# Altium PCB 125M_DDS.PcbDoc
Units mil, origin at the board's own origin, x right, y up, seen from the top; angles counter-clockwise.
Board outline 3579 x 1797 mil, 2 copper layers (Top Layer, Bottom Layer); 23 components, 27 nets, 92 pads, 0 vias.
Unrouted connection lines stored in the file: 63.
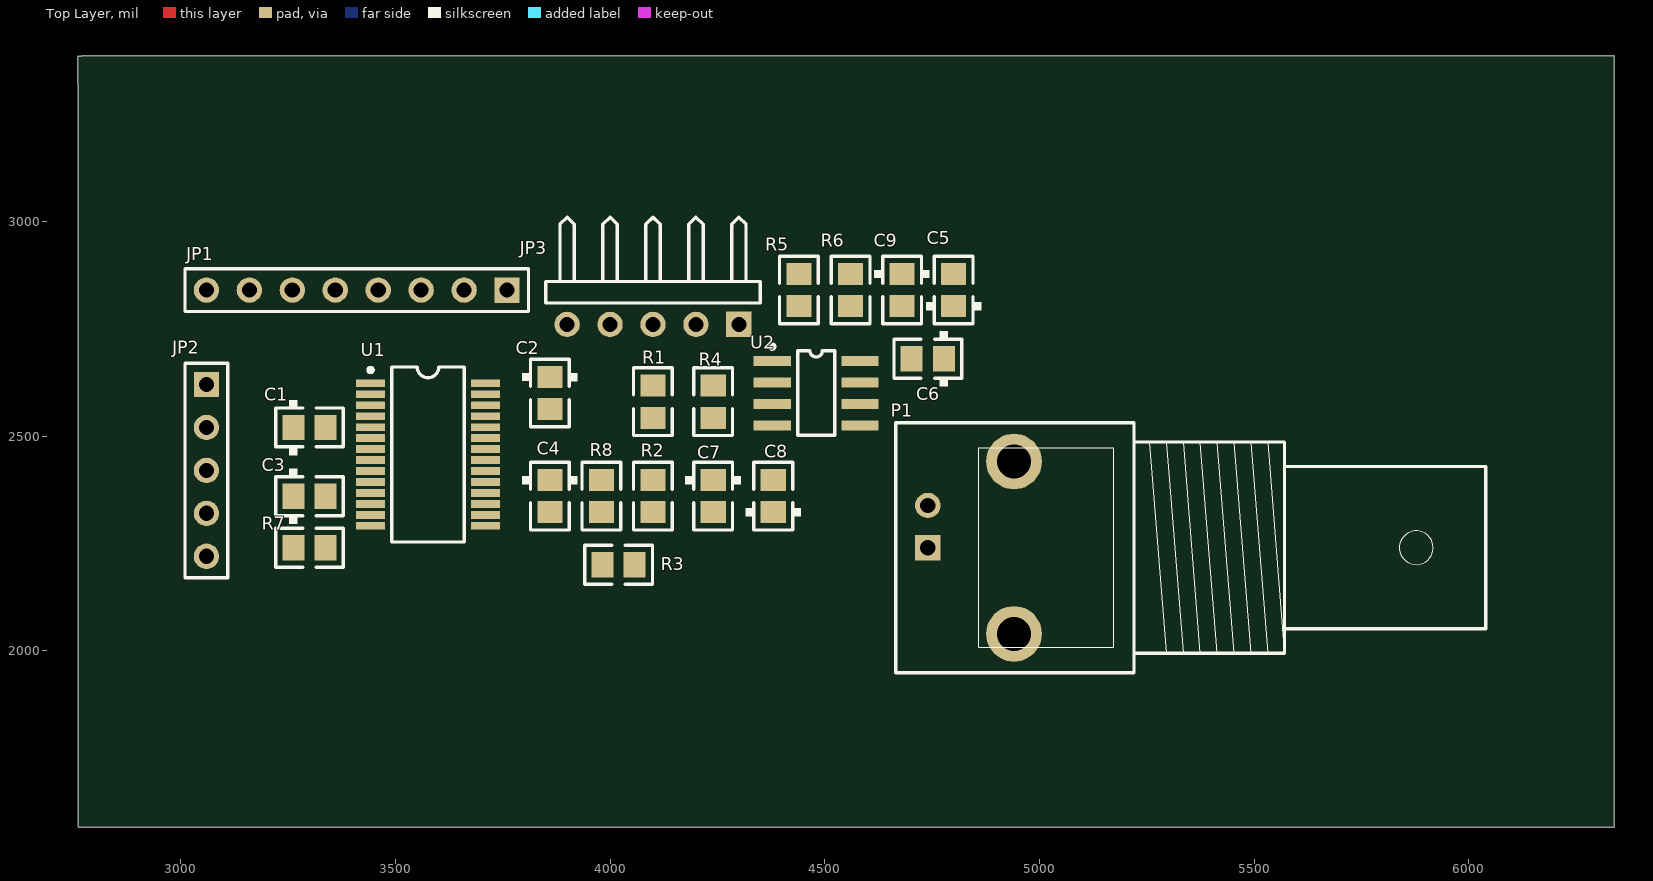
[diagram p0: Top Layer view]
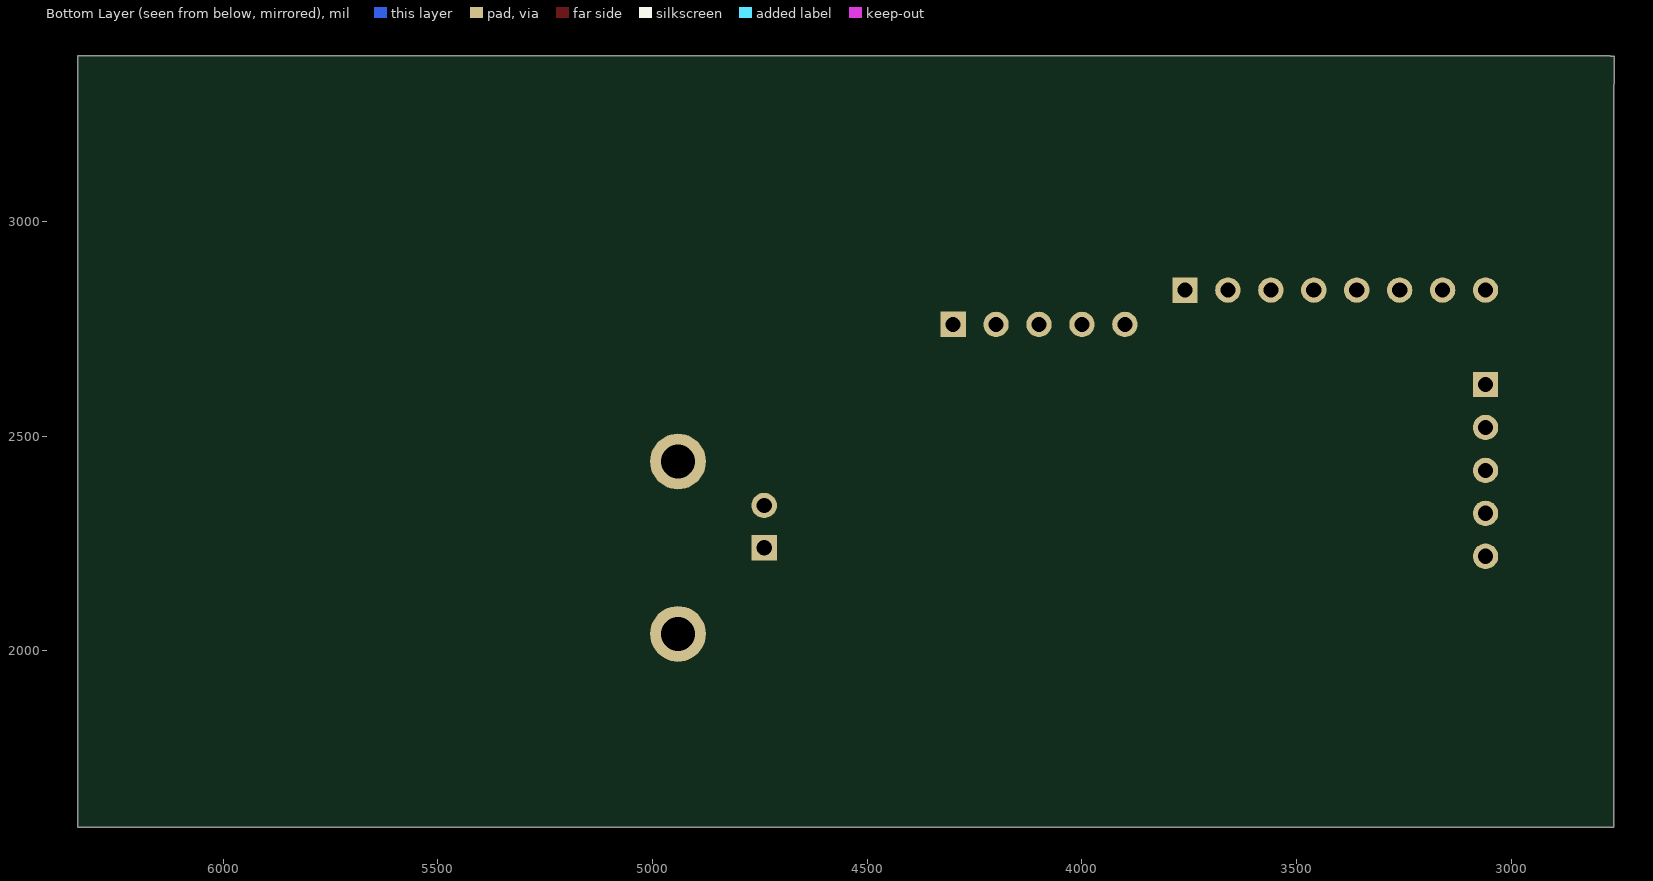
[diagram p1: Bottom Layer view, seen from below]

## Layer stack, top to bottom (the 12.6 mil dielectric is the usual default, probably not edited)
Top Layer: signal copper 1.4
Dielectric: dielectric 12.6, FR-4, Dk 4.8
Bottom Layer: signal copper 1.4

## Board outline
2761,3317 2761,1589 6339,1589 6339,3386 2770,3386 2770,3385 2760,3385 2760,3321

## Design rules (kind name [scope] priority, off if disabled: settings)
Clearance [All] p1: gap=5
ComponentClearance [All] p1: gap=10 collisioncheckmode=0
PolygonConnect [All] p1: connectstyle=Relief reliefconductorwidth=10 reliefentries=4 polygonreliefangle="90 Angle"
RoutingLayers [All] p1: top layer=Horizontal bottom layer=Vertical
RoutingVias [All] p1: holewidth=28 width=50 viastyle="Through Hole" minholewidth=28 minwidth=50 maxholewidth=28 maxwidth=50
SolderMaskExpansion [All] p1: expansion=4
TestPointUsage [All] p1: valid=0 allowmultiple=FALSE
Testpoint [All] p1: side=15 testpointundercomponent=TRUE minsize=40 maxsize=100 preferedsize=60 minholesize=0 maxholesize=40 preferedholesize=32 testpointgrid=1 style=1023 order=-539222988
Width [All] p1: maxlimit=10 minlimit=10 preferedwidth=10
16 further rules are at their usual default settings.

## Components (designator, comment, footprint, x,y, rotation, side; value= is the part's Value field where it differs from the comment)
C1 "100pF" CC2012-0805 3300,2520 r0 top
C2 "100pF" CC2012-0805 3860,2600 r270 top
C3 "100pF" CC2012-0805 3300,2360 r0 top
C4 "100pF" CC2012-0805 3860,2360 r270 top
C5 "180pF" CC2012-0805 4800,2840 r90 top
C6 "100pF" CC2012-0805 4740,2680 r180 top
C7 "470pF" CC2012-0805 4240,2360 r270 top
C8 "100pF" CC2012-0805 4380,2360 r90 top
C9 "90pF" CC2012-0805 4680,2840 r270 top
JP1 "Header 8" HDR1X8 3760,2840 r180 top
JP2 "Header 5" HDR1X5 3060,2620 r270 top
JP3 "Header 5H" HDR1X5H 4300,2760 r180 top
P1 "BNC" "BNC_RA CON" 4740,2240 r180 top
R1 "100K" R2012-0805 4100,2580 r90 top
R2 "100K" R2012-0805 4100,2360 r90 top
R3 "100K" R2012-0805 4020,2200 r0 top
R4 "50" R2012-0805 4240,2580 r90 top
R5 "50" R2012-0805 4440,2840 r270 top
R6 "50" R2012-0805 4560,2840 r90 top
R7 "3.9K" R2012-0805 3300,2240 r180 top
R8 "25" R2012-0805 3980,2360 r270 top
U1 "AD9850BRS" SSO-G28/E4.3 3576,2457 r270 top
U2 "AD8002AR" SO-G8 4480,2600 r270 top

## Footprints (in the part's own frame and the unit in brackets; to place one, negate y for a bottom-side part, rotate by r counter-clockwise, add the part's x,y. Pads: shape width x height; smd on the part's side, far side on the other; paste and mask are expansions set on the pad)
"BNC_RA CON" [mm]
  rect 1.5x1.5 hole 0.9: 1(0,0)
  round 3.3 hole 2: 2(-5.1,5.1) 2(-5.1,-5.1)
  round 1.5 hole 0.9: 2(0,-2.5)
  silkscreen extent -33,-7.4 1.9,7.4
CC2012-0805 [mm]
  rect 1.3x1.5 smd: 1(-0.95,0) 2(0.95,0)
  silkscreen extent -2,-1.65 2,1.64
HDR1X5 [mm]
  rect 1.5x1.5 hole 0.9: 1(0,0)
  round 1.5 hole 0.9: 2(2.54,0) 3(5.08,0) 4(7.62,0) 5(10.16,0)
  silkscreen extent -1.27,-1.27 11.43,1.27
HDR1X5H [mm]
  rect 1.5x1.5 hole 0.9: 1(0,0)
  round 1.5 hole 0.9: 2(2.54,0) 3(5.08,0) 4(7.62,0) 5(10.16,0)
  silkscreen extent -1.27,-6.35 11.43,-1.27
HDR1X8 [mm]
  rect 1.5x1.5 hole 0.9: 1(0,0)
  round 1.5 hole 0.9: 2(2.54,0) 3(5.08,0) 4(7.62,0) 5(10.16,0) 6(12.7,0) 7(15.24,0) 8(17.78,0)
  silkscreen extent -1.27,-1.27 19.05,1.27
R2012-0805 [mm]
  rect 1.3x1.5 smd: 1(-0.95,0) 2(0.95,0)
  silkscreen extent -2,-1.15 2,1.15
SO-G8 [mm]
  rect 0.6x2.2 smd: 1(-1.905,-2.6) 2(-0.635,-2.6) 3(0.635,-2.6) 4(1.905,-2.6) 5(1.905,2.6) 6(0.635,2.6) 7(-0.635,2.6) 8(-1.905,2.6)
  silkscreen extent -2.88,-2.72 2.5,1.1
SSO-G28/E4.3 [mm]
  rect 0.45x1.7 smd: 1(-4.225,-3.4) 2(-3.575,-3.4) 3(-2.925,-3.4) 4(-2.275,-3.4) 5(-1.625,-3.4) 6(-0.975,-3.4) 7(-0.325,-3.4) 8(0.325,-3.4) 9(0.975,-3.4) 10(1.625,-3.4) 11(2.275,-3.4) 12(2.925,-3.4) 13(3.575,-3.4) 14(4.225,-3.4) 15(4.225,3.4) 16(3.575,3.4) 17(2.925,3.4) 18(2.275,3.4) 19(1.625,3.4) 20(0.975,3.4) 21(0.325,3.4) 22(-0.325,3.4) 23(-0.975,3.4) 24(-1.625,3.4) 25(-2.275,3.4) 26(-2.925,3.4) 27(-3.575,3.4) 28(-4.225,3.4)
  silkscreen extent -5.18,-3.52 5.18,2.15

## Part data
C1 C2 C3 C4 C5 C6 C7 C8 C9: library part Cap, "Capacitor"
JP1: "Header, 8-Pin"
JP2: "Header, 5-Pin"
JP3: "Header, 5-Pin,  Right Angle"
P1: "BNC Elbow Connector"
R1 R2 R3 R4 R5 R6 R7 R8: library part Res1, "Resistor"
U1: "CMOS, 125MHz Complete DDS Synthesizer"
U2: "Dual 600MHz, 50mW Current Feedback Amplifier"

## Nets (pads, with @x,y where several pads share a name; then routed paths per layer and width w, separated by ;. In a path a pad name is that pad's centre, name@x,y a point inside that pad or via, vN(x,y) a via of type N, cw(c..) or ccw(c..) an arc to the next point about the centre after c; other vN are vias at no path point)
DACBL: JP2.5 U1.17
DGND: C1.1 C2.1 JP3.4 U1.5 U1.24
FQ_UD: JP2.3 U1.8
GND: C3.1 C4.1 C6.1 C7.1 C8.1 C9.1 JP3.2 P1.1 P1.2@4940.79,2039.21 P1.2@4940.79,2440.79 R3.1 R4.1 R7.2 R8.2 U1.10 U1.19
IN+: R2.1 R3.2 U1.16
IN-: C7.2 R1.1 R2.2 U1.15
NetC5_1: C5.1 P1.2@4740,2338.43 U2.6 U2.7
NetC5_2: C5.2 R5.1 R6.2
NetC9_2: C9.2 R6.1 U2.5
NetJP1_1: JP1.1 U1.25
NetJP1_2: JP1.2 U1.26
NetJP1_3: JP1.3 U1.27
NetJP1_4: JP1.4 U1.28
NetJP1_5: JP1.5 U1.1
NetJP1_6: JP1.6 U1.2
NetJP1_7: JP1.7 U1.3
NetJP1_8: JP1.8 U1.4
NetJP2_1: JP2.1 U1.22
NetJP2_4: JP2.4 U1.9
NetR1_2: R1.2 R4.2 U1.21 U2.3
NetR5_2: R5.2 U2.1 U2.2
NetR7_1: R7.1 U1.12
NetR8_1: R8.1 U1.20
VCC: C3.2 C4.2 C6.2 JP3.3 U1.11 U1.18 U2.8
VDD: C1.2 C2.2 JP3.5 U1.6 U1.23
VSS: C8.2 JP3.1 U2.4
WLCK: JP2.2 U1.7
pads on no net: U1.13 U1.14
